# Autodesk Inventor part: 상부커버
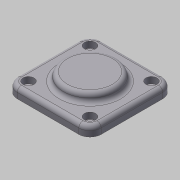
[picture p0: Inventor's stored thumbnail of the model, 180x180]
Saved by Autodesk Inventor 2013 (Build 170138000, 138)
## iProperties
Created: 2018-09
Part Number: 상부커버
Document SubType Name: Modeling
Density: 2.71 g/cm^3
Material: 알루미늄 6061
Mass: 115.614 g
Surface Area: 104.313 cm^2
Volume: 42.662 cm^3
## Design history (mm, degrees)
sketch "스케치1"
  geometry: L1 (30, 22)-(30, -22); L2 (-22, 30)-(22, 30); L3 (-30, -22)-(-30, 22); L4 (22, -30)-(-22, -30); L5 (-30, 0)-(30, 0); L6 (0, 30)-(0, -30); C1 r 20 at (0, 0); A1 r 8 centre (22, 22) between (30, 22) and (22, 30); A2 r 8 centre (-22, 22) between (-22, 30) and (-30, 22); A3 r 8 centre (-22, -22) between (-30, -22) and (-22, -30); A4 r 8 centre (22, -22) between (22, -30) and (30, -22); 2 further points
  constraints: 12 end point, 8 point on circle, 7 midpoint, 7 tangent, 5 centre point, 3 equal radius, 2 horizontal, 1 coincident, 1 vertical
  dimensions: "d23" = 60 distance between parallel lines of L1 L3; "d25" = 60 distance between parallel lines of L4 L2; "d26" = 8 radius of A2; "d27" = 40 diameter of C1
extrude "돌출1" new body sketch "스케치1" distance "d0" = 7; taper "d1" = 0 deg
extrude "돌출2" join sketch "스케치1" distance "d2" = 10; taper "d3" = 0 deg
sketch "스케치2"
  geometry: C1 r 19 at (0, 0); 1 further point
  constraints: 1 centre point, 1 coincident
  dimensions: "d4" = 38 diameter of C1
extrude "돌출3" join sketch "스케치2" distance "d5" = 6; taper "d6" = 0 deg
fillet "모깎기1" dims "d7" = 3
fillet "모깎기2" dims "d8" = 3
sketch "스케치4"
  geometry: L1 (30, 22)-(30, -22) reference; L2 (-22, 30)-(22, 30) reference; L3 (-30, -22)-(-30, 22) reference; L4 (22, -30)-(-22, -30) reference; C1 r 22 at (0, 0) reference; A1 r 8 centre (-22, 22) between (-22, 30) and (-30, 22) reference; A2 r 8 centre (22, 22) between (30, 22) and (22, 30) reference; A3 r 8 centre (-22, 22) between (-22, 30) and (-30, 22) reference; A4 r 8 centre (-22, -22) between (-30, -22) and (-22, -30) reference; A5 r 8 centre (22, -22) between (22, -30) and (30, -22) reference; 5 further points
  constraints: 4 coincident
hole "구멍2" sketch "스케치4" at (-22, 22), (22, 22), (22, -22), (-22, -22) diameter "d28" = 4.5; stored, may be unused: countersink angle "d32" = 90 deg, drill point angle "d34" = 118 deg; dims "d29" = 6, "d30" = 8, "d31" = 4.5, "d33" = 8
fillet "모깎기3" dims "d19" = 3
chamfer "모따기1" distance "d20" = 1; stored, may be unused: second distance "d21" = 2, angle "d22" = 45 deg
node "솔리드1"
node "투영된 루프1"
